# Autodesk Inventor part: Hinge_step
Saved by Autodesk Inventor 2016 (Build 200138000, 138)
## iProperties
Created: 2016-03
Part Number: Hinge_step
Material: Generic
Document SubType Name: Modeling
Designer: bongo_000
Density: 1 g/cm^3
Appearance: Default
Author: bongo_000
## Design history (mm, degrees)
feature "Base1"
feature "Base2"
feature "REVOLVE1" [Base]
body "Solid2"
body "Solid3"
body "Solid1"
